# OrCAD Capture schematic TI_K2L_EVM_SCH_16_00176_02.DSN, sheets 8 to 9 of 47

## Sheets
8 PAGE23 : K2L_USB3.0: size C; title: K2L USB3, TPS USB 5v isolation, USB Type A connector, magnetics, filter, SOC UART 1.8/3.3v, USB to dual UART
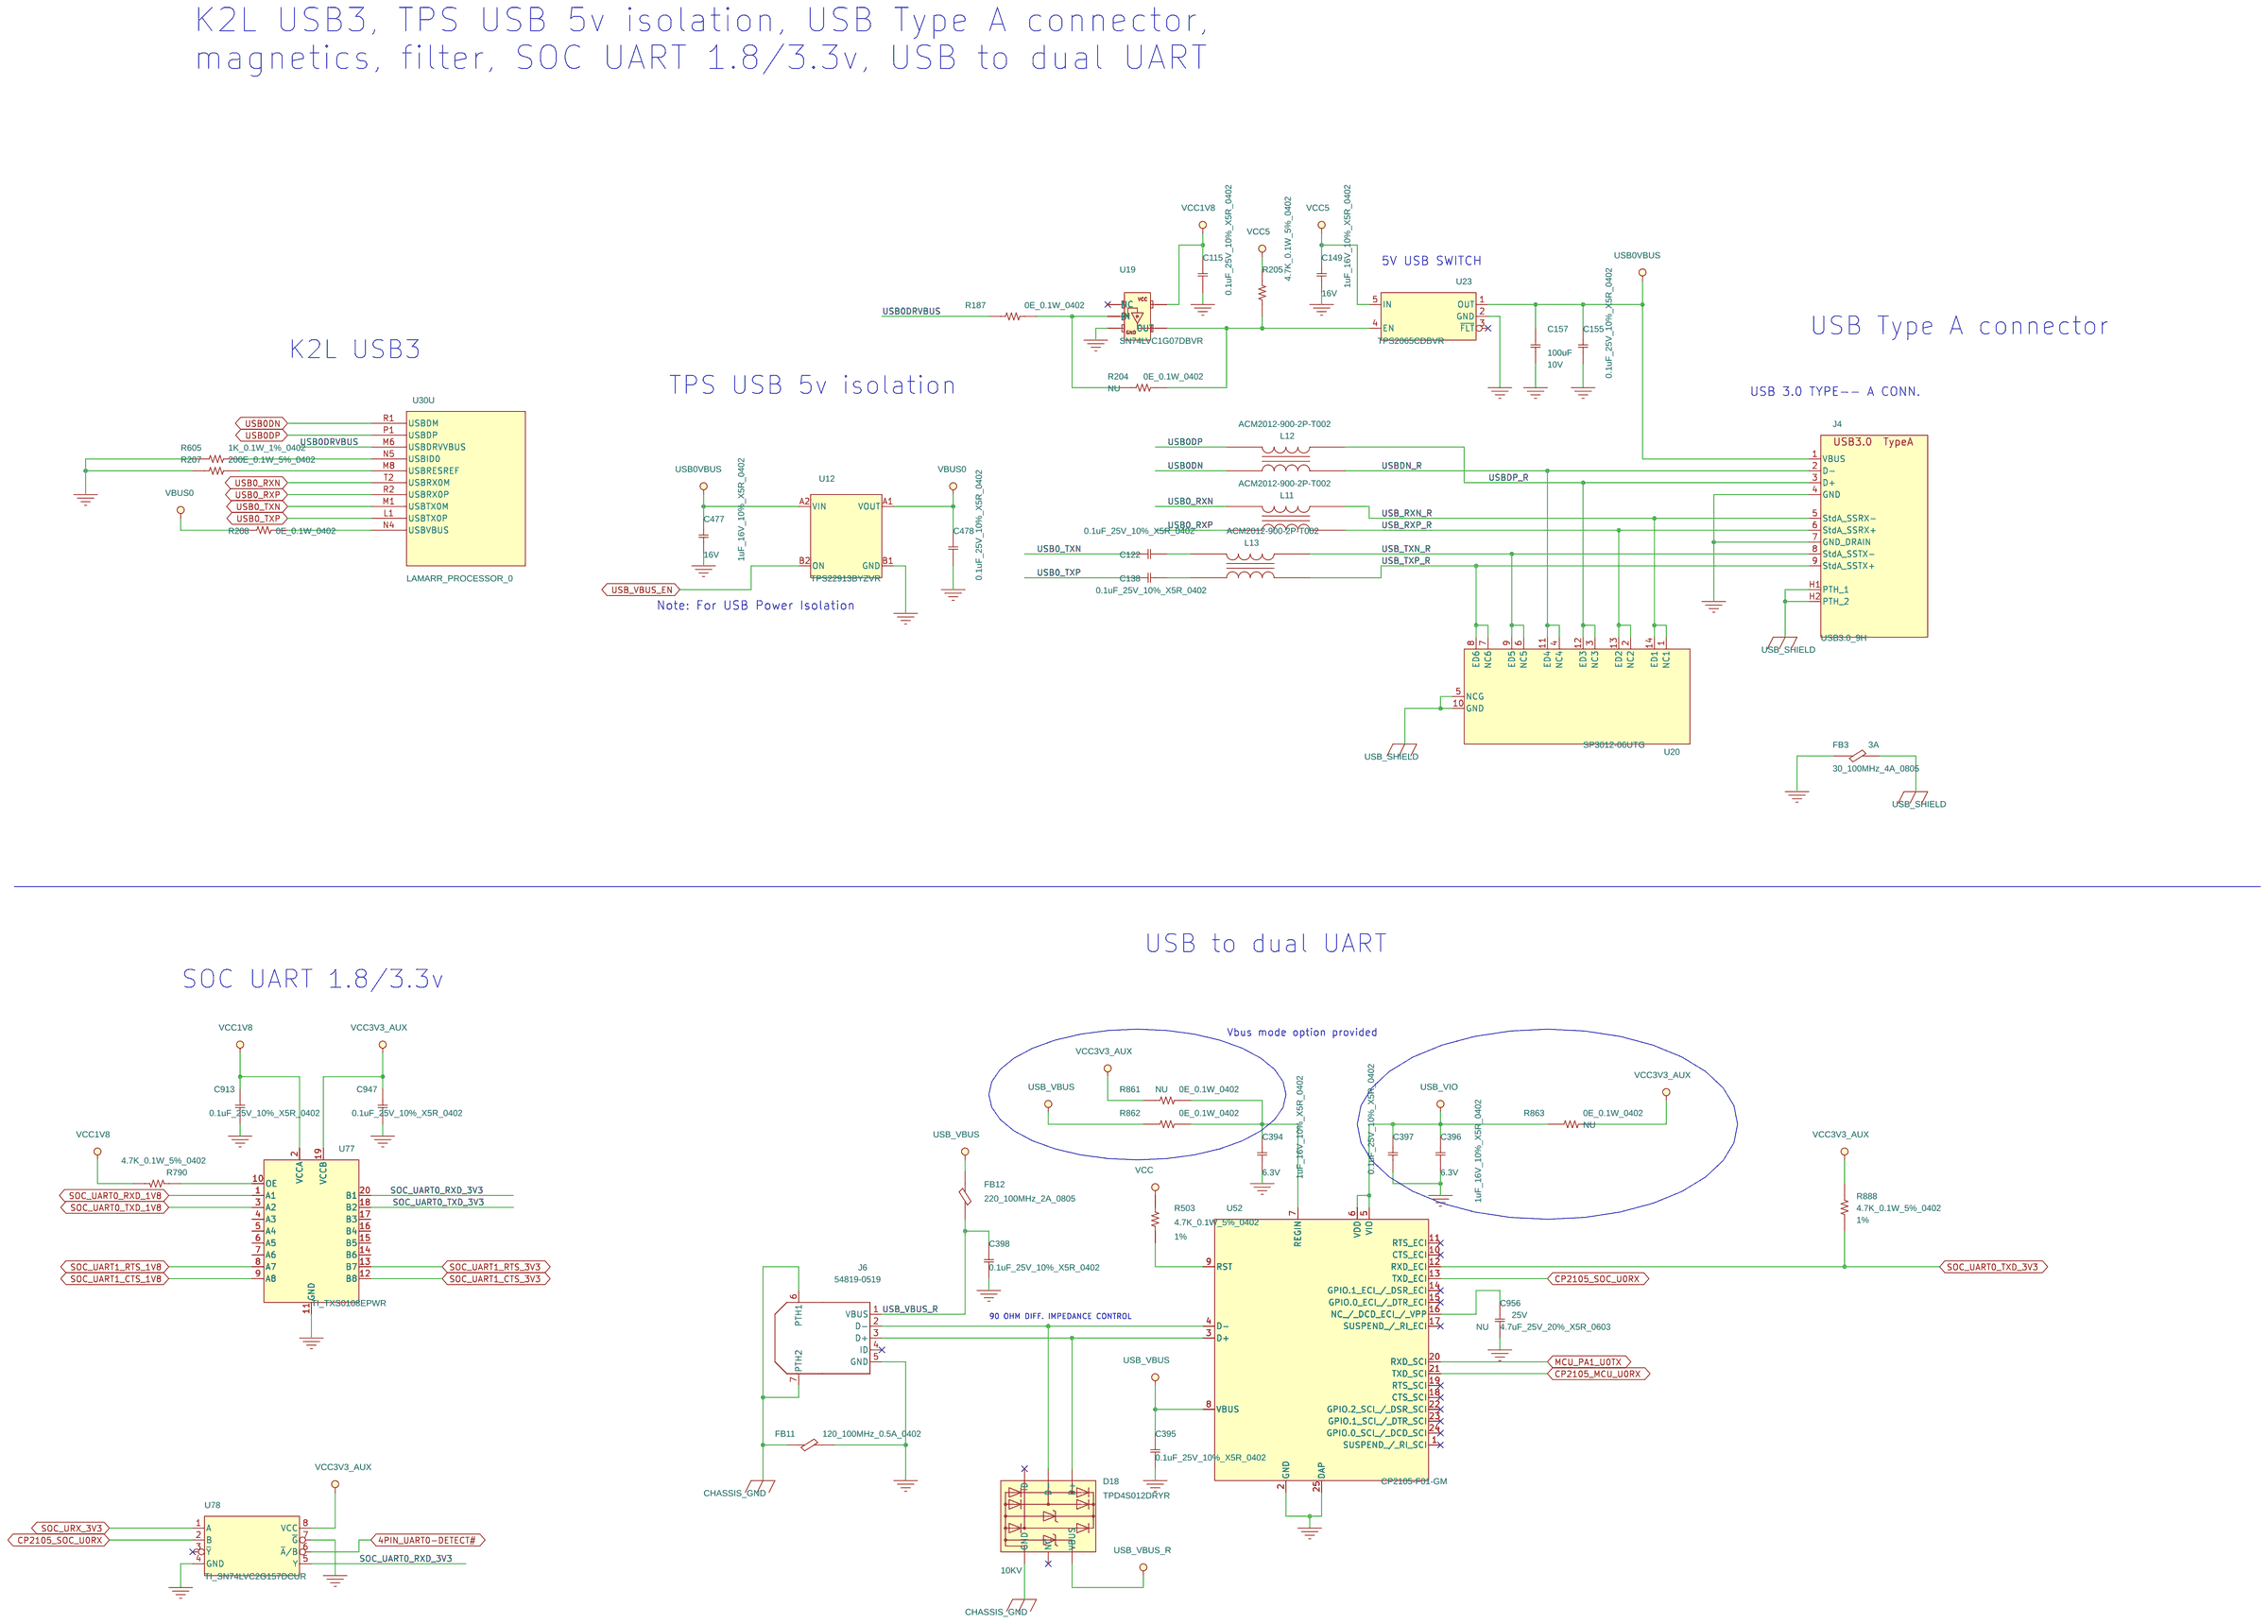
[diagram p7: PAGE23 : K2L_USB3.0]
9 PAGE01 : COVER PAGE_C: title: COVER PAGE
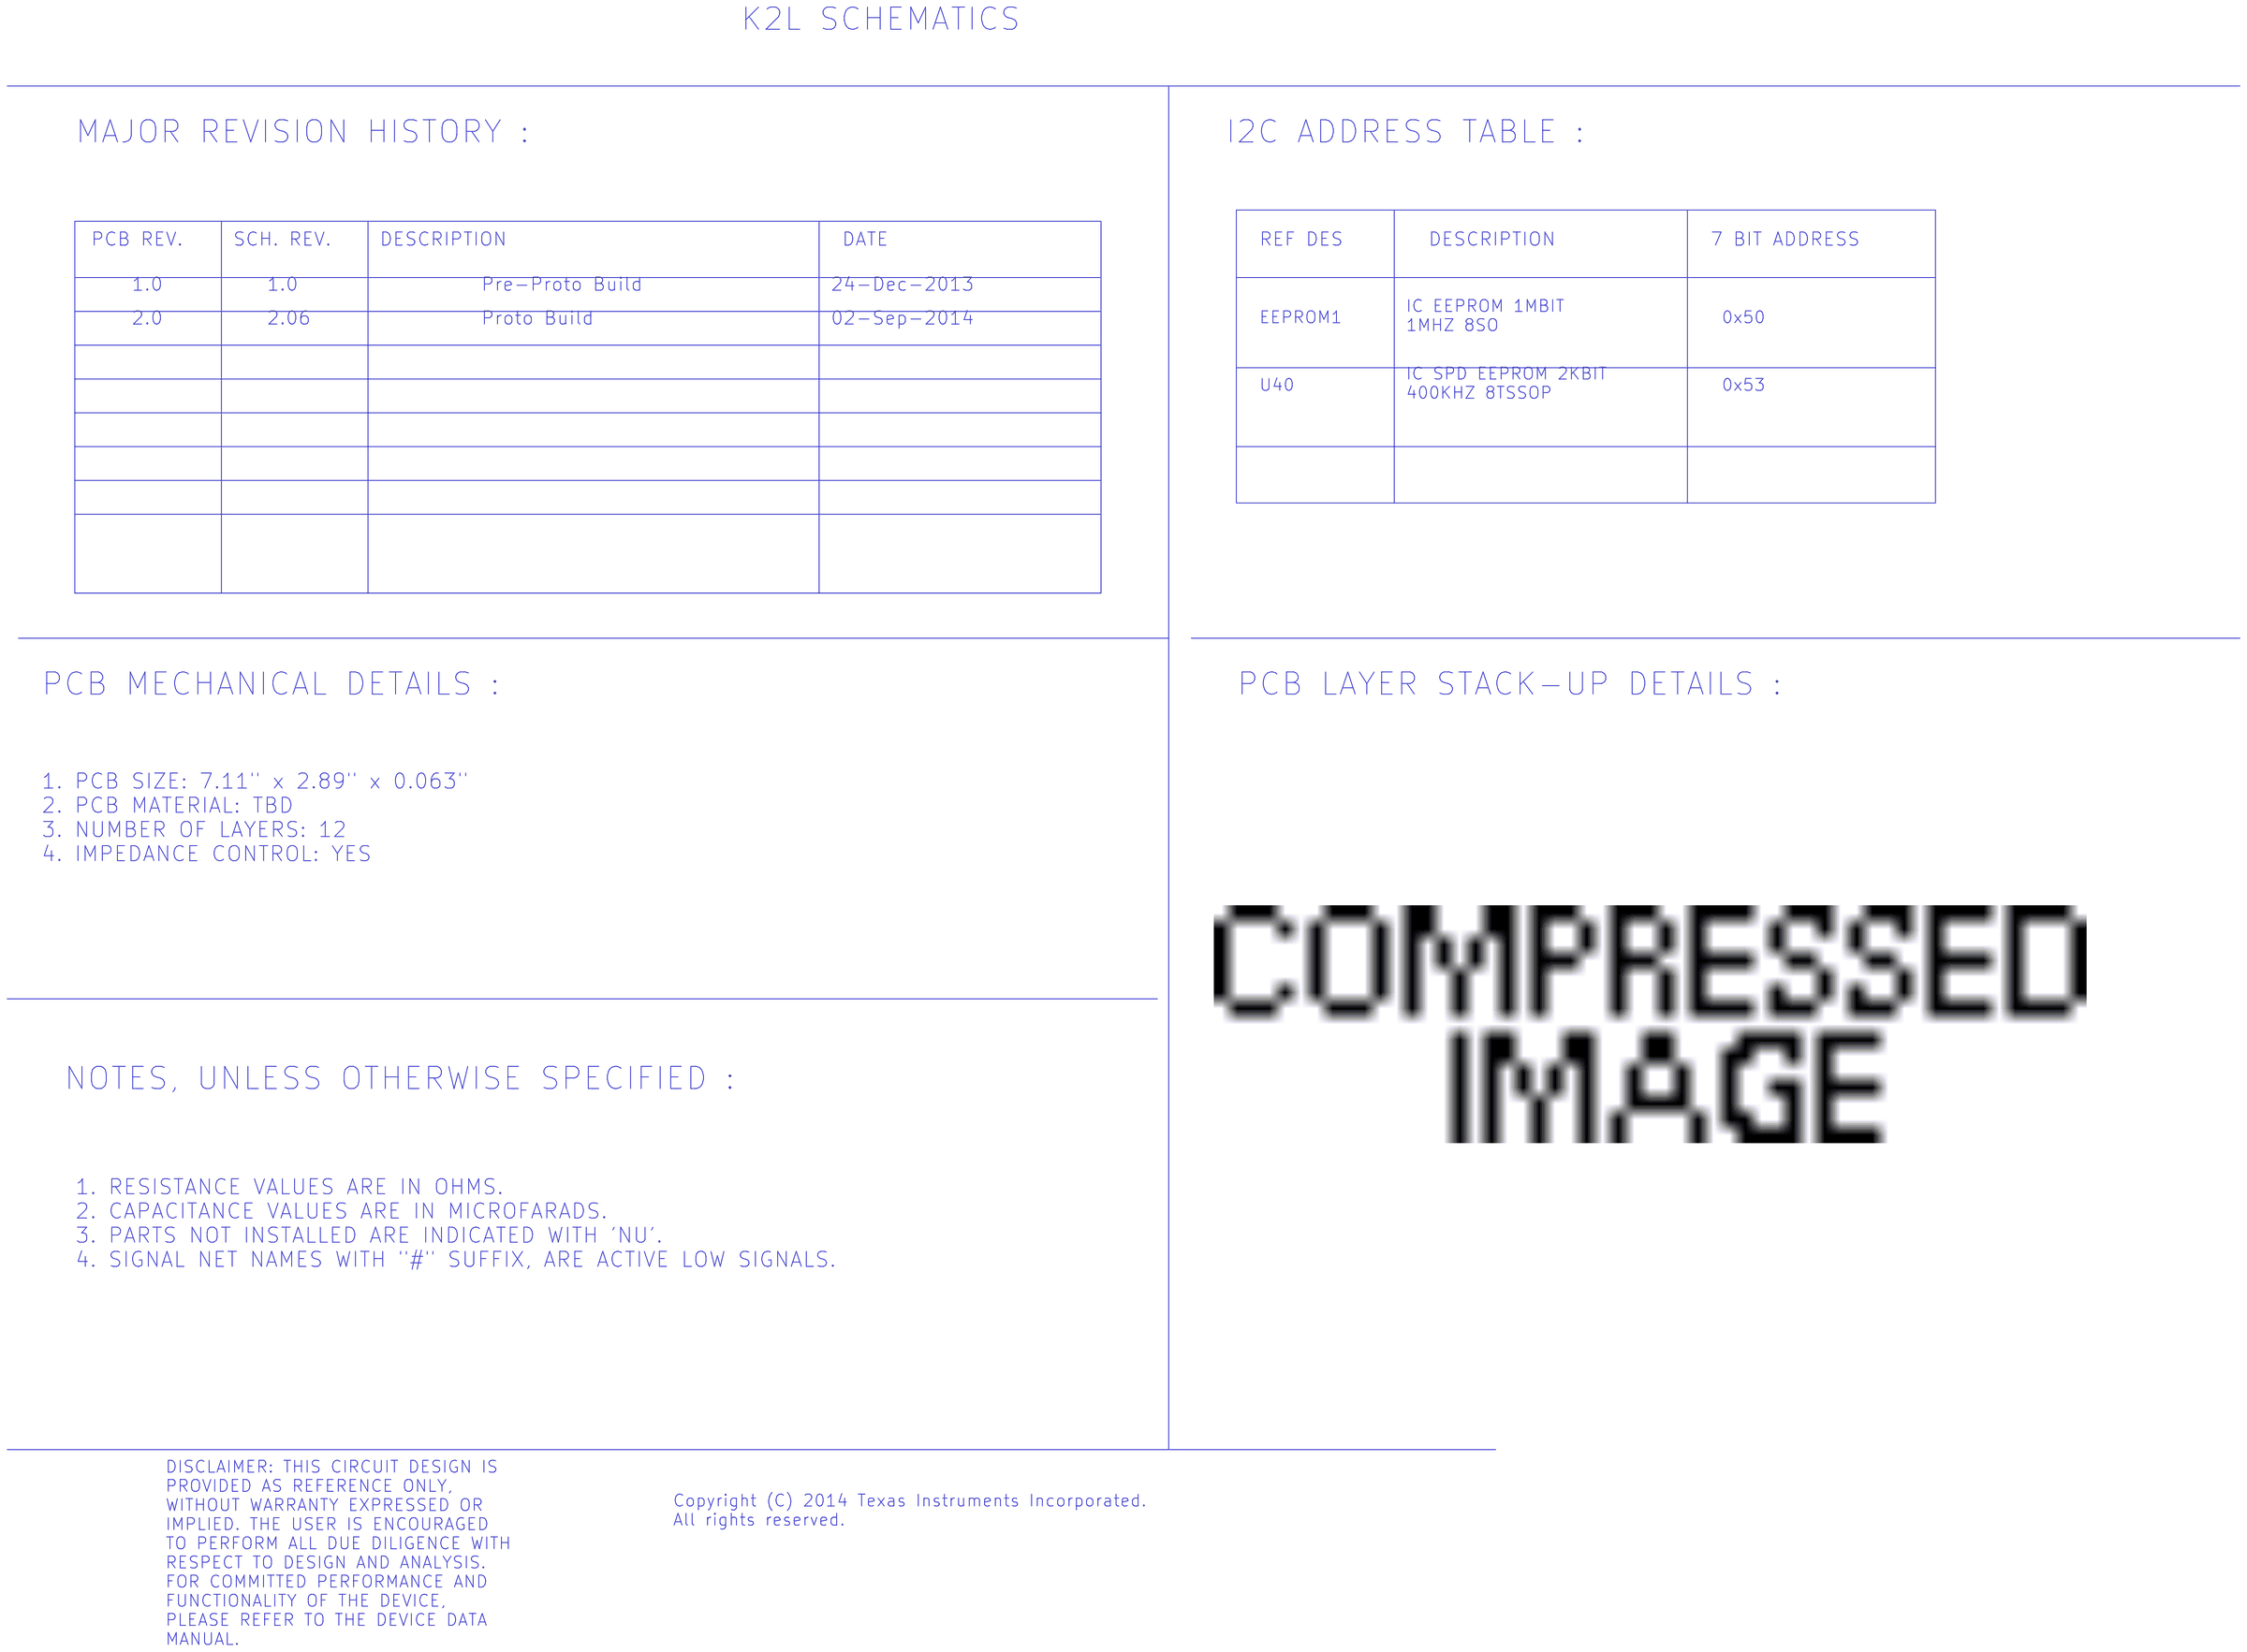
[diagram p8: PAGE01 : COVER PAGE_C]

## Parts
sheet PAGE23 : K2L_USB3.0
C115  0.1uF_25V_10%_X5R_0402  [C0402]
C122  0.1uF_25V_10%_X5R_0402  [C0402]
C138  0.1uF_25V_10%_X5R_0402  [C0402]
C149  1uF_16V_10%_X5R_0402  [C0402]
C155  0.1uF_25V_10%_X5R_0402  [C0402]
C157  100uF  [CC1210]
C394  1uF_16V_10%_X5R_0402  [C0402]
C395  0.1uF_25V_10%_X5R_0402  [C0402]
C396  1uF_16V_10%_X5R_0402  [C0402]
C397  0.1uF_25V_10%_X5R_0402  [C0402]
C398  0.1uF_25V_10%_X5R_0402  [C0402]
C477  1uF_16V_10%_X5R_0402  [C0402]
C478  0.1uF_25V_10%_X5R_0402  [C0402]
C913  0.1uF_25V_10%_X5R_0402  [C0402]
C947  0.1uF_25V_10%_X5R_0402  [C0402]
C956  4.7uF_25V_20%_X5R_0603  [C0603]
D18  TPD4S012DRYR  [SON_6P_20_59X39]
FB3  30_100MHz_4A_0805  [L0805]
FB11  120_100MHz_0.5A_0402  [L0402]
FB12  220_100MHz_2A_0805  [L0805]
J4  USB3.0_9H  [USB_9P_UEA1112C-4HK1-4H]
J6  54819-0519  [MOL54819-0519]
L11  ACM2012-900-2P-T002  [ACM2012]
L12  ACM2012-900-2P-T002  [ACM2012]
L13  ACM2012-900-2P-T002  [ACM2012]
R187  0E_0.1W_0402  [R0402]
R204  0E_0.1W_0402  [R0402]
R205  4.7K_0.1W_5%_0402  [R0402]
R207  200E_0.1W_5%_0402  [R0402]
R208  0E_0.1W_0402  [R0402]
R503  4.7K_0.1W_5%_0402  [R0402]
R605  1K_0.1W_1%_0402  [R0402]
R790  4.7K_0.1W_5%_0402  [R0402]
R861  0E_0.1W_0402  [R0402]
R862  0E_0.1W_0402  [R0402]
R863  0E_0.1W_0402  [R0402]
R888  4.7K_0.1W_5%_0402  [R0402]
U12  TPS22913BYZVR  [dsbga50p_0p9x0p9_4]
U19  SN74LVC1G07DBVR  [SOT-23_5P]
U20  SP3012-06UTG  [DFN50P350X135X55-14N]
U23  TPS2065CDBVR  [SOT-23_5P]
U52  CP2105-F01-GM  [PVQFN50P400X400_24_PWP]
U77  TI_TXS0108EPWR  [SOIC_20P_26_256x252]
U78  TI_SN74LVC2G157DCUR  [SOIC_8P_20_79X122]
sheet PAGE24 : K2L_JTAG
U30  LAMARR_PROCESSOR_0  [SKTBGA_Z3566_SS900-RHFB-BGA080]  (sections A,B,C,D,E,F,G,H,I,J,K,L,M,N,O,P,Q,R,S,T,U)

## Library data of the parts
C115 C155 C395 C397 C398 C478 C913 C947 = 11_C_12: CAP CER 0.1UF 25V 10% X5R 0402; Alt Mfg: Taiyo Yuden; Distributor_name: DIGIKEY; Distributor_part_number: 445-4964-1-ND; EIC Part#: 03_00470_02; Manufacture: TDK Corporation; Manufacture Part Number: C1005X5R1E104K050BC; Manufacture(English): TDK Corporation; Manufacture_Part_Number: GRM155R61E104KA87D; Manufacturer: TDK Corporation; Manufacturer_Part_No: C1005X5R1E104K050BC; Mfg: Murata Electronics North America; Mfg Part#: 03_00470_02; Mfr_name: TDK Corporation; Mfr_part_number: C1005X5R1E104K050BC; Oper. Temp. Range: -55°C ~ 85°C; Package: 0402; Price @ 1: 0.10000; Price @ 1K: 0.00960; ProcessType: SMT; RoHS: Yes; Tolerance: 10%; Vendor: DIGIKEY; Vendor Part#: 445-4964-1-ND; Vendor_Part_No: 445-4964-1-ND; eI Part#: 03_00470_02
C122 C138 = 11_C_12: CAP CER 0.1UF 25V 10% X5R 0402; Alt Mfg: Taiyo Yuden; Distributor_name: DIGIKEY; Distributor_part_number: 445-4964-1-ND; EIC Part#: 03_00470_02; MOUNTED: <MOUNTED>; Manufacture: TDK Corporation; Manufacture Part Number: C1005X5R1E104K050BC; Manufacture(English): TDK Corporation; Manufacture_Part_Number: GRM155R61E104KA87D; Manufacturer: TDK Corporation; Manufacturer_Part_No: C1005X5R1E104K050BC; Mfg: Murata Electronics North America; Mfg Part#: 03_00470_02; Mfr_name: TDK Corporation; Mfr_part_number: C1005X5R1E104K050BC; Oper. Temp. Range: -55°C ~ 85°C; Package: 0402; Price @ 1: 0.10000; Price @ 1K: 0.00960; ProcessType: SMT; RoHS: Yes; Tolerance: 10%; Vendor: DIGIKEY; Vendor Part#: 445-4964-1-ND; Vendor_Part_No: 445-4964-1-ND; eI Part#: 03_00470_02
C149 C477 = 11_C_12: CAP CER 1UF 16V 10% X5R 0402; Characteristic: <Characteristic>; Distributor_name: DIGIKEY; Distributor_part_number: 445-4978-1-ND; EIC Part#: 03_00355_04; Manufacture: TDK Corporation; Manufacture Part Number: C1005X5R1C105K050BC; Manufacture(English): TDK Corporation; Manufacture_Part_Number: C1005X5R1C105K050BC; Manufacturer: TDK Corporation; Manufacturer_Part_No: C1005X5R1C105K050BC; Mfg: TDK Corporation; Mfg Part#: C1005X5R1C105K050BC; Mfr_name: TDK Corporation; Mfr_part_number: C1005X5R1C105K050BC; Oper. Temp. Range: -55C to 85C; Package: 0402; Price @ 1: 0.12000; Price @ 10K: 0.01600; Price @ 1K: 0.02200; ProcessType: SMT; RoHS: Yes; Tolerance: 10%; Vendor: DIGIKEY; Vendor Part#: 445-4978-1-ND; Vendor_Part_No: 445-4978-1-ND; Voltage: 16V; eI Part#: 03_00355_04
C157 = Cap_Ceramic: CAP CER 100UF 10V 20% X5R 1210; Characteristic: <Characteristic>; Distributor_name: DIGIKEY; Distributor_part_number: 587-1965-1-ND; EIC Part#: 03_00145_02; Manufacture: Taiyo Yuden; Manufacture Part Number: LMK325BJ107MM-T; Manufacture(English): Taiyo Yuden; Manufacture_Part_Number: LMK325BJ107MM-T; Manufacturer: Taiyo Yuden; Manufacturer_Part_No: LMK325BJ107MM-T; Mfg: Taiyo Yuden; Mfg Part#: LMK325BJ107MM-T; Mfr_name: Taiyo Yuden; Mfr_part_number: LMK325BJ107MM-T; Oper. Temp. Range: -55C to 85C; Package: 1210; ProcessType: SMT; RoHS: Yes; Tolerance: 20%; Vendor: DigiKey; Vendor Part#: 587-1965-1-ND; Vendor_Part_No: 587-1965-1-ND; Voltage: 10V; eI Part#: 03_00145_02
C394 C396 = 11_C_12: CAP CER 1UF 16V 10% X5R 0402; Characteristic: <Characteristic>; Distributor_name: DIGIKEY; Distributor_part_number: 445-4978-1-ND; EIC Part#: 03_00355_04; Manufacture: TDK Corporation; Manufacture Part Number: C1005X5R1C105K050BC; Manufacture(English): TDK Corporation; Manufacture_Part_Number: C1005X5R1C105K050BC; Manufacturer: TDK Corporation; Manufacturer_Part_No: C1005X5R1C105K050BC; Mfg: TDK Corporation; Mfg Part#: C1005X5R1C105K050BC; Mfr_name: TDK Corporation; Mfr_part_number: C1005X5R1C105K050BC; Oper. Temp. Range: -55C to 85C; Package: 0402; Price @ 1: 0.12000; Price @ 10K: 0.01600; Price @ 1K: 0.02200; ProcessType: SMT; RoHS: Yes; Tolerance: 10%; Vendor: DIGIKEY; Vendor Part#: 445-4978-1-ND; Vendor_Part_No: 445-4978-1-ND; Voltage: 6.3V; eI Part#: 03_00355_04
C956 = 11_C_0: CAP CER 4.7UF 25V 20% X5R 0603; Distributor_name: DIGIKEY; Distributor_part_number: 1276-1903-2-ND; EIC Part#: 03_00592_01; Manufacture: Samsung; Manufacture Part Number: CL10A475MA8NQNC; Manufacture(English): Samsung; Manufacture_Part_Number: CL10A475MA8NQNC; Manufacturer: Samsung; Manufacturer_Part_No: CL10A475MA8NQNC; Mfg: Samsung; Mfg Part#: CL10A475MA8NQNC; Mfr_name: Samsung; Mfr_part_number: CL10A475MA8NQNC; Mounting Status: NU; Mounting_Status: NU; Oper. Temp. Range: -55C to 85C; Package: 0603; ProcessType: SMT; RoHS: Yes; Tolerance: 10%; Vendor: DIGIKEY; Vendor Part#: 1276-1903-2-ND; Vendor_Part_No: 1276-1903-2-ND; Voltage: 25V; eI Part#: 03_00592_01
D18 = 130_TVS_SON6_TPD4S012DRY_0: IC 4CH ESD SOLUTION W/CLAMP 6SON; Characteristic: 10KV; Distributor_name: DIGIKEY; Distributor_part_number: 296-24244-1-ND; EIC Part#: 01_01160_01; Manufacture: TI; Manufacture(English): TI; Manufacturer: TI; Mfg: TI; Mfg Part#: 01_01160_01; Mfr_name: TI; Package: SON6; Part_Number: 1300004466-01; Price @ 1: 0.78000; Price @ 10K: 0.23625; Price @ 1K: 0.24097; ProcessType: SMT; Vendor: DIGIKEY; Vendor Part#: 296-24244-1-ND; Vendor_Part_No: 296-24244-1-ND; eI Part#: 01_01160_01
FB3 = 1212_BEAD_0: FERRITE CHIP 30 OHM 0805; Advansus_Part_Number: 09G012030000; Characteristic: 3A; Distributor_name: DIGIKEY; Distributor_part_number: 490-1052-1-ND; EIC Part#: 04_00406_01; Manufacture: Murata; Manufacture Part Number: BLM21PG300SN1D; Manufacture(English): Murata; Manufacture_Part_Number: BLM21PG300SN1D; Manufacturer: Murata; Manufacturer_Part_No: BLM21PG300SN1D; Mfg: Murata Electronics North America; Mfg Part#: 04_00406_01; Mfr_name: Murata; Mfr_part_number: BLM21PG300SN1D; Package: 0805; Part_Number: 1212302000; Price @ 1: 0.13000; Price @ 10K: 0.02820; Price @ 1K: 0.03309; ProcessType: SMT; Tolerance: 25%; Vendor: DIGIKEY; Vendor Part#: 490-1052-1-ND; Vendor_Part_No: 490-1052-1-ND; eI Part#: 04_00406_01
FB11 = 1212_BEAD_0: FERRITE CHIP 120 OHM 500MA 0402; Distributor_name: DIGIKEY; Distributor_part_number: 490-1005-1-ND; EIC Part#: 04_00075_01; Manufacture: Murata; Manufacture Part Number: BLM15AG121SN1D; Manufacture(English): Murata; Manufacture_Part_Number: BLM15AG121SN1D; Manufacturer: Murata; Manufacturer_Part_No: BLM15AG121SN1D; Mfg: Murata Electronics North America; Mfg Part#: BLM15AG121SN1D; Mfr_name: Murata; Mfr_part_number: BLM15AG121SN1D; Oper. Temp. Range: -55C to 85C; Package: 0402; Price @ 1: 0.10000; Price @ 10K: 0.02016; Price @ 1K: 0.02905; ProcessType: SMT; RoHS: Yes; Tolerance: 25%; Vendor: DIGIKEY; Vendor Part#: 490-1005-1-ND; Vendor_Part_No: 490-1005-1-ND; eI Part#: 04_00075_01
FB12 = 1212_BEAD_0: FERRITE CHIP 220 OHM 0805; Distributor_name: DIGIKEY; Distributor_part_number: 490-1054-1-ND; EIC Part#: 04_00016_01; Manufacture: Murata; Manufacture Part Number: BLM21PG221SN1D; Manufacture(English): Murata; Manufacture_Part_Number: BLM21PG221SN1D; Manufacturer: Murata; Manufacturer_Part_No: BLM21PG221SN1D; Mfg: Murata Electronics North America; Mfg Part#: 04_00016_01; Mfr_name: Murata; Mfr_part_number: BLM21PG221SN1D; Oper. Temp. Range: -55C to 85C; Package: 0805; Price @ 1: 0.11000; Price @ 10K: 0.02368; Price @ 1K: 0.03093; ProcessType: SMT; RoHS: Yes; Vendor: DIGIKEY; Vendor Part#: 490-1054-1-ND; Vendor_Part_No: 490-1054-1-ND; eI Part#: 04_00016_01
J4 = 1654_USB3-A_9P_UEA1112C-4HK1_4: CONN USB 3.0 RCPT ST A R/A; AVL_Part: AVL; Distributor_name: DIGIKEY; Distributor_part_number: 609-4661-ND; EIC Part#: TBD; Manufacture: FCI; Manufacture Part Number: 10117835-001LF; Manufacture(English): FCI; Manufacturer: FCI; Manufacturer_Part_No: 10117835-001LF; Mfg Part#: TBD; Mfr_name: FCI; Mfr_part_number: 10117835-001LF; Package: USB9P; ProcessType: DIP; Vendor: DIGIKEY; Vendor Part#: 609-4661-ND; Vendor_Part_No: 609-4661-ND; eI Part#: TBD
J6 = 678038020_0: MINI USB TYPE B CONNECTOR, RCPT 5POS THD; Distributor_name: ELEMENT14; Distributor_part_number: 2133828; EIC Part#: 09_00954_01; Manufacture: Molex Inc; Manufacture(English): Molex Inc; Manufacturer: Molex Inc; Mfg: Molex Inc; Mfg Part#: 09_00954_01; Mfr_name: Molex Inc; Price @ 1: 2.40000; Price @ 10K: 1.77000; Price @ 1K: 1.77000; Vendor: ELEMENT14; Vendor_Part_No: 2133828; eI Part#: 09_00954_01
L11-L13 = CHOKE_CM_0: CHOKE COMM MODE 90 OHM .4A SMD; Distributor_name: DIGIKEY; Distributor_part_number: 445-2207-1-ND; EIC Part#: TBD; Manufacture: TDK Corporation; Manufacture(English): TDK Corporation; Manufacturer: TDK Corporation; Mfg: TDK Corporation; Mfg Part#: TBD; Mfr_name: TDK Corporation; Package: 0805; Price @ 1: 0.50000; Price @ 10K: 0.19040; Price @ 1K: 0.24640; RoHS: Yes; Vendor: DIGIKEY; Vendor_Part_No: 445-2207-1-ND; eI Part#: TBD
R187 R208 R862 = 10_R_0: RES 0.0 OHM 1/10W JUMP 0402 SMD; Alt Mfg: Yageo; Distributor_name: DIGIKEY; Distributor_part_number: P0.0JCT-ND; EIC Part#: 02_00019_01; Manufacture: Panasonic - ECG; Manufacture Part Number: ERJ-2GE0R00X; Manufacture(English): Panasonic - ECG; Manufacture_Part_Number: ERJ-2GE0R00X; Manufacturer: Panasonic - ECG; Manufacturer_Part_No: ERJ-2GE0R00X; Mfg Part#: 02_00019_01; Mfr_name: Panasonic - ECG; Mfr_part_number: ERJ-2GE0R00X; Oper. Temp. Range: -55C to 125C; Package: 0402; ProcessType: SMT; Remark: Alt part is 1/16W; RoHS: Yes; Tolerance: 5%; Vendor: DIGIKEY; Vendor Part#: P0.0JCT-ND; Vendor_Part_No: P0.0JCT-ND; eI Part#: 02_00019_01
R204 = 10_R_0: RES 0.0 OHM 1/10W JUMP 0402 SMD; Alt Mfg: Yageo; Distributor_name: DIGIKEY; Distributor_part_number: P0.0JCT-ND; EIC Part#: 02_00019_01; Manufacture: Panasonic - ECG; Manufacture Part Number: ERJ-2GE0R00X; Manufacture(English): Panasonic - ECG; Manufacture_Part_Number: ERJ-2GE0R00X; Manufacturer: Panasonic - ECG; Manufacturer_Part_No: ERJ-2GE0R00X; Mfg Part#: 02_00019_01; Mfr_name: Panasonic - ECG; Mfr_part_number: ERJ-2GE0R00X; Mounting: NU; Mounting Status: NU; Mounting_Status: NU; Oper. Temp. Range: -55C to 125C; Package: 0402; ProcessType: SMT; Remark: Alt part is 1/16W; RoHS: Yes; Tolerance: 5%; Vendor: DIGIKEY; Vendor Part#: P0.0JCT-ND; Vendor_Part_No: P0.0JCT-ND; eI Part#: 02_00019_01
R205 R503 R790 R888 = 10_R_0: RES 4.7K OHM 1/10W 5% 0402 SMD; Alt Mfg: Yageo; Alt Mfg Part#: RC0402JR-074K7L; Distributor_name: DIGIKEY; Distributor_part_number: P4.7KJCT-ND; EIC Part#: 02_00023_01; Manufacture: Panasonic - ECG; Manufacture Part Number: ERJ-2GEJ472X; Manufacture(English): Panasonic - ECG; Manufacture_Part_Number: ERJ-2GEJ472X; Manufacturer: Panasonic - ECG; Manufacturer_Part_No: ERJ-2GEJ472X; Mfg Part#: 02_00023_01; Mfr_name: Panasonic - ECG; Mfr_part_number: ERJ-2GEJ472X; Oper. Temp. Range: -55C to 125C; Package: 0402; ProcessType: SMT; Remark: Alt part is 1/16W; RoHS: Yes; Tolerance: 1%; Vendor: DIGIKEY; Vendor Part#: P4.7KJCT-ND; Vendor_Part_No: P4.7KJCT-ND; eI Part#: 02_00023_01
R207 = 10_R_0: RES 200 OHM 1/10W 5% 0402 SMD; Characteristic: 1%; Distributor_name: DIGIKEY; Distributor_part_number: P200JCT-ND; EIC Part#: 02_00022_01; Manufacture: Panasonic - ECG; Manufacture Part Number: ERJ-2GEJ201X; Manufacture(English): Panasonic - ECG; Manufacture_Part_Number: ERJ-2GEJ201X; Manufacturer: Panasonic - ECG; Manufacturer_Part_No: ERJ-2GEJ201X; Mfg: Panasonic Electronic Components; Mfg Part#: 02_00022_01; Mfr_name: Panasonic - ECG; Mfr_part_number: ERJ-2GEJ201X; Package: 0402; Part_Number: 1000000859-02; Price @ 1: 0.10000; Price @ 10K: 0.00248; Price @ 1K: 0.00480; ProcessType: SMT; RoHS: Yes; Tolerance: 5%; Vendor: DIGIKEY; Vendor Part#: P200JTR-ND; Vendor_Part_No: P200JCT-ND; eI Part#: 02_00266_01
R605 = 10_R_0: RES 1.00K OHM 1/10W 1% 0402 SMD; Alt Mfg: Yageo; Distributor_name: DIGIKEY; Distributor_part_number: P1.00KLCT-ND; EIC Part#: 02_00045_01; MOUNTED: <MOUNTED>; Manufacture: Panasonic - ECG; Manufacture Part Number: ERJ-2RKF1001X; Manufacture(English): Panasonic - ECG; Manufacture_Part_Number: ERJ-2RKF1001X; Manufacturer: Panasonic - ECG; Manufacturer_Part_No: ERJ-2RKF1001X; Mfg Part#: 02_00045_01; Mfr_name: Panasonic - ECG; Mfr_part_number: ERJ-2RKF1001X; Oper. Temp. Range: -55C to 125C; Package: 0402; ProcessType: SMT; RoHS: Yes; Tolerance: 1%; Vendor: DIGIKEY; Vendor Part#: P1.00KLCT-ND; Vendor_Part_No: P1.00KLCT-ND; eI Part#: 02_00045_01
R861 R863 = 10_R_0: RES 0.0 OHM 1/10W JUMP 0402 SMD; Alt Mfg: Yageo; Distributor_name: DIGIKEY; Distributor_part_number: P0.0JCT-ND; EIC Part#: 02_00019_01; Manufacture: Panasonic - ECG; Manufacture Part Number: ERJ-2GE0R00X; Manufacture(English): Panasonic - ECG; Manufacture_Part_Number: ERJ-2GE0R00X; Manufacturer: Panasonic - ECG; Manufacturer_Part_No: ERJ-2GE0R00X; Mfg Part#: 02_00019_01; Mfr_name: Panasonic - ECG; Mfr_part_number: ERJ-2GE0R00X; Mounting Status: NU; Mounting_Status: NU; Oper. Temp. Range: -55C to 125C; Package: 0402; ProcessType: SMT; Remark: Alt part is 1/16W; RoHS: Yes; Tolerance: 5%; Vendor: DIGIKEY; Vendor Part#: P0.0JCT-ND; Vendor_Part_No: P0.0JCT-ND; eI Part#: 02_00019_01
U12 = TPS22913B: IC LOAD SWITCH 5V 4DSBGA; Distributor_name: DIGIKEY; Distributor_part_number: 296-29697-1-ND; EIC Part#: 01_01129_01; Manufacture: TI; Manufacture(English): TI; Manufacturer: TI; Mfg: TI; Mfg Part#: 01_01129_01; Mfr_name: TI; Price @ 1: 0.89000; Price @ 10K: 0.27000; Price @ 1K: 0.27540; Vendor: DIGIKEY; Vendor_Part_No: 296-29697-1-ND; eI Part#: 01_01129_01
U19 = 14S_TI_SN74LVC1G07_SOT-23-5: IC BUFF/DVR NON-INVERT SOT235; Distributor_name: DIGIKEY; Distributor_part_number: 296-8485-1-ND; EIC Part#: 01_00844_01; Manufacture: TI; Manufacture(English): TI; Manufacturer: TI; Mfg: TI; Mfg Part#: 01_00844_01; Mfr_name: TI; Oper. Temp. Range: -40°C ~ 85°C; Package: SOT-23-5; Price @ 1: 0.24000; Price @ 10K: 0.11000; Price @ 1K: 0.12700; ProcessType: SMT; RoHS: Yes; Vendor: DIGIKEY; Vendor Part#: 296-8485-1-ND; Vendor_Part_No: 296-8485-1-ND; eI Part#: 01_00844_01
U20 = SP3012-06UTG: TVS DIODE ARRARY 5V 6CH 14UDFN; Distributor_name: DIGIKEY; Distributor_part_number: F5914CT-ND; EIC Part#: 01_01141_01; Manufacture: Littelfuse Inc; Manufacture(English): Littelfuse Inc; Manufacturer: Littelfuse Inc; Mfg: Littelfuse Inc; Mfg Part#: 01_01141_01; Mfr_name: Littelfuse Inc; Price @ 1: 1.16000; Price @ 10K: 0.44800; Price @ 1K: 0.49600; RoHS: Yes; Vendor: DIGIKEY; Vendor Part#: F5914CT-ND; Vendor_Part_No: F5914CT-ND; eI Part#: 01_01141_01
U23 = 141_TI_TPS2065CDBVR_0: IC PWR SW USB 1.48A 1CH SOT23-5; AVL_Part: AVL; Distributor_name: DIGIKEY; Distributor_part_number: 296-35606-1-ND; EIC Part#: TBD; Manufacture: TI; Manufacture(English): TI; Manufacturer: TI; Mfg: TI; Mfg Part#: TBD; Mfr_name: TI; Oper. Temp. Range: -40°C ~ 85°C; Package: SOT-23-5; Price @ 1: 1.57000; Price @ 1K: 0.93524; ProcessType: SMT; RoHS: Yes; Vendor: DIGIKEY; Vendor_Part_No: 296-35606-1-ND; eI Part#: 01_01128_01
U52 = CP2105_3: IC SGL USB-DL UART BRIDGE 24QFN; Distributor_name: DIGIKEY; Distributor_part_number: 336-2009-5-ND; EIC Part#: 01_01127_01; Manufacture: Silicon Laboratories Inc; Manufacture(English): Silicon Laboratories Inc; Manufacturer: Silicon Laboratories Inc; Mfg: Silicon Laboratories Inc; Mfg Part#: 01_01127_01; Mfr_name: Silicon Laboratories Inc; Price @ 1: 1.49000; Price @ 10K: 1.30000; Price @ 1K: 1.30000; Vendor: DIGIKEY; Vendor_Part_No: 336-2009-5-ND; eI Part#: TBD
U77 = 141_TI_TXS0108EPWR_0: IC 8BIT NON-INV TRANSLTR 20TSSOP; Distributor_name: DIGIKEY; Distributor_part_number: 296-23011-1-ND; EIC Part#: 01_00472_01; Manufacture: TI; Manufacture Part Number: TXS0108EPWR; Manufacture(English): TI; Manufacture_Part_Number: TXS0108EPWR; Manufacturer: TI; Manufacturer_Part_No: TXS0108EPWR; Mfg: TI; Mfg Part#: 01_00472_01; Mfr_name: TI; Mfr_part_number: TXS0108EPWR; Oper. Temp. Range: -40°C ~ 85°C; Package: TSSOP20; Part_Number: 1410020326; Price @ 1: 2.30000; Price @ 10K: 0.90000; Price @ 1K: 0.91800; ProcessType: SMT; RoHS: Yes; Vendor: DIGIKEY; Vendor Part#: 296-23011-1-ND; Vendor_Part_No: 296-23011-1-ND; eI Part#: TBD
U78 = 141_TI_SN74LVC2G157_0: IC MULTIPLEXER DATA SEL US8; Distributor_name: DIGIKEY; Distributor_part_number: 296-12605-1-ND; EIC Part#: 01_01117_01; Manufacture: TI; Manufacture Part Number: SN74LVC2G157DCUR; Manufacture(English): TI; Manufacture_Part_Number: SN74LVC2G157DCUR; Manufacturer: TI; Manufacturer_Part_No: SN74LVC2G157DCUR; Mfg: TI; Mfg Part#: 01_01117_01; Mfr_name: TI; Mfr_part_number: SN74LVC2G157DCUR; Oper. Temp. Range: -40°C ~ 85°C; Package: VSSOP8; Price @ 1: 0.70000; Price @ 10K: 0.24650; Price @ 1K: 0.28050; ProcessType: SMT; RoHS: Yes; Vendor: DIGIKEY; Vendor Part#: 296-32322-2-ND; Vendor_Part_No: 296-12605-1-ND; eI Part#: TBD
U30 = LAMARR_PROCESSOR_7: LAMARR-SoC 900BGA 4DSP + 2ARM; Color: Default; Distributor_name: TBD; Distributor_part_number: TBD; EIC Part#: TBD; Location X-Coordinate: 0; Location Y-Coordinate: 0; Manufacture: TI; Manufacture Part Number: TCI6630K2L; Manufacture(English): TI; Manufacture_Part_Number: TCI6630K2L; Manufacturer: TI; Manufacturer_Part_No: TCI6630K2L; Mfg: TI; Mfg Part#: TBD; Mfr_name: TI; Mfr_part_number: LAMARR-SoC; Price @ 1: TBD; Price @ 10K: TBD; Price @ 1K: TBD; Primitive: DEFAULT; SPLIT_INST: TRUE; SWAP_INFO: (S1+S2+S3+S4+S5+S6+S7+S8+S9+S10+S11+S12+S13+S14+S15+S16+S17+S18+S19+S20+S21); Vendor: TBD; Vendor_Part_No: TBD; eI Part#: TBD

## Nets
GND: C115.2 C149.2 C155.2 C157.2 C394.2 C395.2 C396.2 C397.2 C398.2 C477.2 C478.2 C913.2 C947.2 C956.2 FB3.2 FB11.2 J4.4(GND) J4.7(GND_DRAIN) J6.5(GND) R207.1 R605.1 U12.B1(GND) U19.3 U23.2(GND) U52.2(GND) U52.25(DAP) U77.11(GND) U78.4(GND) U78.7(~{G}) ; also on sheet 1 2 3 4 5 6 10 11 12 13 14 15 16 17 18 19 20 21 22 24 25 26 27 28 29 33 34 35 36 37 40 41 42 43 45 46 47
VBUS0: C478.1 R208.1 U12.A1(VOUT)
VCC1V8: C115.1 C913.1 R790.2 U19.5 U77.2(VCCA) ; also on sheet 2 6 11 19 21 22 25 26 27 29 33 34 36 37 41
VCC3V3_AUX: C947.1 R861.1 R863.2 R888.2 U77.19(VCCB) U78.8(VCC) ; also on sheet 2 4 6 11 12 13 16 18 19 22 25 26 27 28 29 33 35 37 40 45 47
VCC5: C149.1 R205.2 U23.5(IN) ; also on sheet 26 34 37
4PIN_UART0-DETECT#: U78.6(~{A}/B) ; also on sheet 6
CHASSIS_GND: D18.4(GND) FB11.1 J6.6(PTH1) J6.7(PTH2) ; also on sheet 10
CP2105_MCU_U0RX: U52.21(TXD_SCI) ; also on sheet 5
CP2105_SOC_U0RX: U52.13(TXD_ECI) U78.2(B)
MCU_PA1_U0TX: U52.20(RXD_SCI) ; also on sheet 4 5
SOC_UART0_RXD_1V8: U77.1(A1) ; also on sheet 29
SOC_UART0_RXD_3V3: U77.20(B1) U78.5(Y)
SOC_UART0_TXD_1V8: U77.3(A2) ; also on sheet 29
SOC_UART0_TXD_3V3: R888.1 U52.12(RXD_ECI) U77.18(B2) ; also on sheet 5 6
SOC_UART1_CTS_1V8: U77.9(A8) ; also on sheet 29
SOC_UART1_CTS_3V3: U77.12(B8) ; also on sheet 26
SOC_UART1_RTS_1V8: U77.8(A7) ; also on sheet 29
SOC_UART1_RTS_3V3: U77.13(B7) ; also on sheet 26
SOC_URX_3V3: U78.1(A) ; also on sheet 6
USB0_RXN: L11.1 U30.T2(USBRX0M)
USB0_RXP: L11.2 U30.R2(USBRX0P)
USB0_TXN: C122.2 U30.M1(USBTX0M)
USB0_TXP: C138.2 U30.L1(USBTX0P)
USB0DN: L12.2 U30.R1(USBDM)
USB0DP: L12.1 U30.P1(USBDP)
USB0DRVBUS: R187.1 U30.M6(USBDRVVBUS)
USB0VBUS: C155.1 C157.1 C477.1 J4.1(VBUS) U12.A2(VIN) U23.1(OUT)
USB_RXN_R: J4.5(StdA_SSRX-) L11.4 U20.1(NC1) U20.14(ED1)
USB_RXP_R: J4.6(StdA_SSRX+) L11.3 U20.2(NC2) U20.13(ED2)
USB_SHIELD: FB3.1 J4.H1(PTH_1) J4.H2(PTH_2) U20.5(NCG) U20.10(GND)
USB_TXN_R: J4.8(StdA_SSTX-) L13.4 U20.6(NC5) U20.9(ED5)
USB_TXP_R: J4.9(StdA_SSTX+) L13.3 U20.7(NC6) U20.8(ED6)
USB_VBUS: C395.1 FB12.2 R862.1 U52.8(VBUS)
USB_VBUS_EN: U12.B2(ON) ; also on sheet 37
USB_VBUS_R: C398.1 D18.6(VBUS) FB12.1 J6.1(VBUS)
USB_VIO: C396.1 C397.1 R503.2 R863.1 U52.5(VIO) U52.6(VDD)
USBDN_R: J4.2(D-) L12.3 U20.4(NC4) U20.11(ED4)
USBDP_R: J4.3(D+) L12.4 U20.3(NC3) U20.12(ED3)
N17727623: R207.2 U30.M8(USBRESREF)
N17727874: R208.2 U30.N4(USBVBUS)
N17728949: D18.2(D-) J6.2(D-) U52.4(D-)
N17728951: D18.1(D+) J6.3(D+) U52.3(D+)
N17729046: C394.1 R861.2 R862.2 U52.7(REGIN)
N17733257: R790.1 U77.10(OE)
N18402683: R187.2 R204.1 U19.2(IN)
N18402697: R204.2 R205.1 U19.4(OUT) U23.4(EN)
N19296244: C956.1 U52.16(NC_/_DCD_ECI_/_VPP)
N19296683: R503.1 U52.9(RST)
N19621760: R605.2 U30.N5(USBID0)
N19652271: C122.1 L13.1
N19652276: C138.1 L13.2

Not connected (* = marked no-connect by the designer): D18 3(ID)* 5(NC)*; J6 4(ID)*; U19 1(NC)*; U23 3(~{FLT})*; U52 1(SUSPEND_/_RI_SCI)* 10(CTS_ECI)* 11(RTS_ECI)* 14(GPIO.1_ECI_/_DSR_ECI)* 15(GPIO.0_ECI_/_DTR_ECI)* 17(SUSPEND_/_RI_ECI)* 18(CTS_SCI)* 19(RTS_SCI)* 22(GPIO.2_SCI_/_DSR_SCI)* 23(GPIO.1_SCI_/_DTR_SCI)* 24(GPIO.0_SCI_/_DCD_SCI)*; U77 4(A3) 5(A4) 6(A5) 7(A6) 14(B6) 15(B5) 16(B4) 17(B3); U78 3(~{Y})*

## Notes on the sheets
sheet 8
- K2L USB3, TPS USB 5v isolation, USB Type A connector,
  magnetics, filter, SOC UART 1.8/3.3v, USB to dual UART
- 5V USB SWITCH
- USB Type A connector
- K2L USB3
- TPS USB 5v isolation
- USB 3.0 TYPE-- A CONN.
- Note: For USB Power Isolation
- USB to dual UART
- SOC UART 1.8/3.3v
- Vbus mode option provided
- 90 OHM DIFF. IMPEDANCE CONTROL
sheet 9
- K2L SCHEMATICS
- MAJOR REVISION HISTORY :
- I2C ADDRESS TABLE :
- PCB REV.
- SCH. REV.
- DESCRIPTION
- DATE
- REF DES
- DESCRIPTION
- 7 BIT ADDRESS
- 1.0
- 1.0
- Pre-Proto Build
- 24-Dec-2013
- IC EEPROM 1MBIT
  1MHZ 8SO
- 2.0
- 2.06
- Proto Build
- 02-Sep-2014
- EEPROM1
- 0x50
- IC SPD EEPROM 2KBIT
  400KHZ 8TSSOP
- U40
- 0x53
- PCB MECHANICAL DETAILS :
- PCB LAYER STACK-UP DETAILS :
- 1. PCB SIZE: 7.11" x 2.89" x 0.063"
  2. PCB MATERIAL: TBD
  3. NUMBER OF LAYERS: 12
  4. IMPEDANCE CONTROL: YES
- NOTES, UNLESS OTHERWISE SPECIFIED :
- 1. RESISTANCE VALUES ARE IN OHMS.
  2. CAPACITANCE VALUES ARE IN MICROFARADS.
  3. PARTS NOT INSTALLED ARE INDICATED WITH 'NU'.
  4. SIGNAL NET NAMES WITH "#" SUFFIX, ARE ACTIVE LOW SIGNALS.
- DISCLAIMER: THIS CIRCUIT DESIGN IS
  PROVIDED AS REFERENCE ONLY,
  WITHOUT WARRANTY EXPRESSED OR
  IMPLIED. THE USER IS ENCOURAGED
  TO PERFORM ALL DUE DILIGENCE WITH
  RESPECT TO DESIGN AND ANALYSIS.
  FOR COMMITTED PERFORMANCE AND
  FUNCTIONALITY OF THE DEVICE,
  PLEASE REFER TO THE DEVICE DATA
  MANUAL.
- Copyright (C) 2014 Texas Instruments Incorporated.
  All rights reserved.
